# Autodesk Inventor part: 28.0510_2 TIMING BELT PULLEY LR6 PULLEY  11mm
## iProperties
Created: 2007-06
Part Number: 28.0510_2 TIMING BELT PULLEY LR6 PULLEY  11mm
Document SubType Name: Modeling
Designer: Andy Moles
Material: Aluminum-6061
Density: 2.71 g/cm^3
Author: Andy Moles
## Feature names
1. Revolution1
2. Extrusion1
3. Circular Pattern1
4. Extrusion2
5. Mirror1
6. Extrusion3
